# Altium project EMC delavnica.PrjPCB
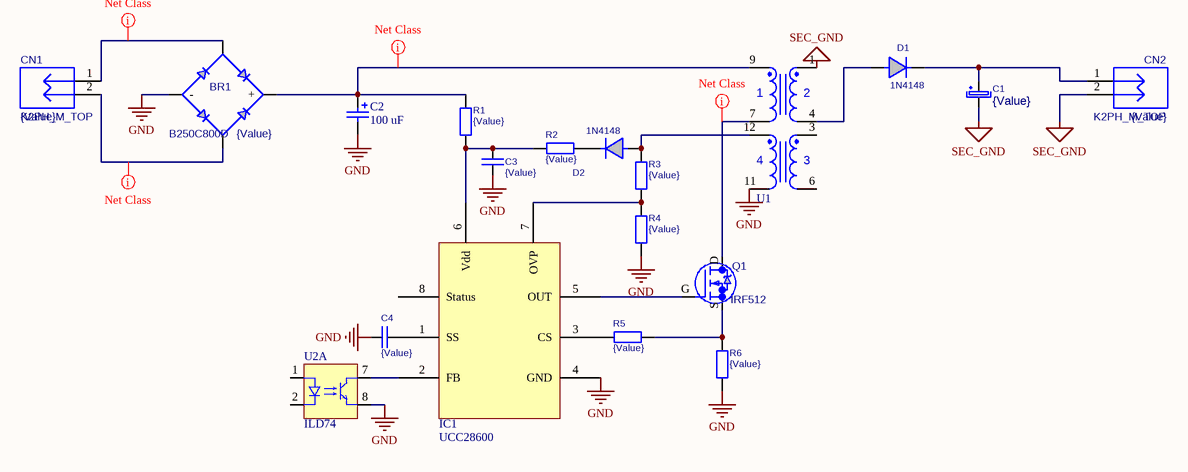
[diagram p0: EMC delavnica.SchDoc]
1 sheet, 19 parts. Net scope: global (net labels, ports and power ports of the same name join across sheets).
Board file: EMC delavnica.PcbDoc

## Sheet EMC delavnica.SchDoc
size A4

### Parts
BR1  B250C800D  value {Value}  [DIP4M-GREZ]
C1  {Value}  [C-SMD-ELKO-D]
C2  100 uF  [WCAP-ATG8_18x31.5x7.5x0.8]
C3  {Value}  [C0805]
C4  {Value}  [C0805]
CN1  K2PH_M_TOP  value {Value}  [K2PH_M_TOP]
CN2  K2PH_M_TOP  value {Value}  [K2PH_M_TOP]
D1  1N4148  [MELF3517N_DIO]
D2  1N4148  [MELF3517N_DIO]
IC1  UCC28600  [SOIC127P600X175-8M]
Q1  IRF512  [TO-220AB vertical]
R1  {Value}  [R0805]
R2  {Value}  [R0805]
R3  {Value}  [R0805]
R4  {Value}  [R0805]
R5  {Value}  [R0805]
R6  {Value}  [R0805]
U1  760871113  [WE-UOST_EE16/8/5]  (value not drawn)
U2  ILD74  [DIP8]  (part A of 2)

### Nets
GND: BR1.GND(-) C2.2 C3.2 C4.1 IC1.4(GND) R4.2 R6.2 U1.11 U2.8(E)
SEC_GND: C1.2 CN2.2 U1.1
NetBR1_AC1: BR1.AC1 CN1.1
NetBR1_AC2: BR1.AC2 CN1.2
NetBR1_PLUS: BR1.PLUS(+) C2.1 R1.1 U1.9
NetC1_1: C1.1 CN2.1 D1.K
NetC3_1: C3.1 IC1.6(Vdd) R1.2 R2.1
NetC4_2: C4.2 IC1.1(SS)
NetD1_A: D1.A U1.4
NetD2_A: D2.A R3.1 U1.12
NetD2_K: D2.K R2.2
NetIC1_2: IC1.2(FB) U2.7(C)
NetIC1_3: IC1.3(CS) R5.1
NetIC1_5: IC1.5(OUT) Q1.G
NetIC1_7: IC1.7(OVP) R3.2 R4.1
NetQ1_D: Q1.D U1.7
NetQ1_S: Q1.S R5.2 R6.1

Not connected (* = marked no-connect by the designer): IC1 8(Status); U1 3 6; U2 1(A) 2(K)

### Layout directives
net class HighV: NetBR1_AC1, NetBR1_AC2, NetBR1_PLUS, NetQ1_D

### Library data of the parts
C1 = C+: Capacitor Polarized
C2 = WCAP-ATG8, 860011381012: WCAP-ATG8 Aluminum Electrolytic Capacitors, 100 uF; RatedVoltage: 400V
C3 C4 = C: Capacitor
D1 D2 = 1N4148: pin to pad: A>2 K>1
IC1 = UCC28600: Flyback power supply controller from TI
Q1 = IRF512: Value: {Value}
R1-R6 = R
U1 = 760871113: WE-UOST Universal Offline Standard Transformers, size EE16/8/5, 1310 uH , 140:6:6:16 , 12.5 W; Inductance: 1310 uH; OutputPower: 12.5 W
U2 = ILD74: Optocoupler, Phototransistor Output, Dual Channel, TTL Compatible, Pb-free; Note: Coupling Capacitance, 0.5 pF; Note: Transfer Ratio, 35 % Typical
